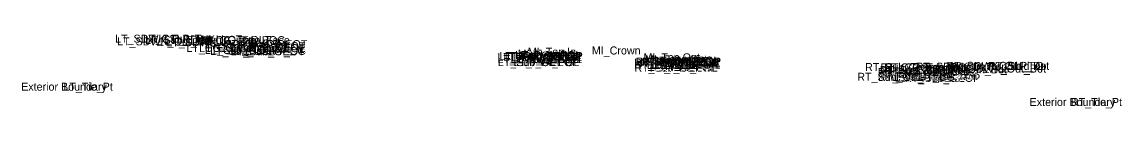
# Model space of a CAD drawing. Extents: x -26 to 6300, y -10 to 9528.
# Drawn here: x 1074.9 to 1212.4, y 7509.6 to 7518.8 of the extents above; entities that cross this region are included whole.
import ezdxf

# ---------------------------------------------------------------- set-up
doc = ezdxf.new("R2010")
doc.units = 0
doc.layers.add('Default', color=7, linetype='Continuous')

msp = doc.modelspace()

# ---------------------------------------------------------------- texts
at = {"layer": 'Default'}
for s, p in [('LT_SDWK_Out_Top', (1086.58, 7517.78)), ('LT_CSLP_Pnt', (1090.1, 7517.78)), ('LT_Sub_Trench_Out_DLT', (1090.32, 7517.63)), ('LT_SDWK_In_Top', (1092.74, 7517.68)), ('LT_CG_Top_BOC', (1096.81, 7517.59)), ('LT_CG_Top_Face', (1097.34, 7517.59)), ('LT_SDWK_Out_Bot', (1086.83, 7517.44)), ('LT_SDWK_In_Bot', (1092.99, 7517.34)), ('LT_CG1_Shelf_Out', (1095.48, 7516.62)), ('LT_CG_Bot_BOC', (1097.09, 7516.6)), ('LT_Sub_OEOP', (1097.79, 7516.38)), ('LT_CG_Top_Gut', (1097.87, 7517.09)), ('LT_Sub_OEOT_CG', (1098.44, 7516.25)), ('LT_PV2_OEOT', (1100.99, 7516.84)), ('LT_PV3_OEOT', (1100.99, 7516.59)), ('LT_Sub_OEOT', (1101.04, 7516.21)), ('LT_PV1_OEOT', (1101.23, 7517.09)), ('LT_CG_Bot_IE', (1101.34, 7516.5)), ('MI_Crown', (1146.15, 7516.3)), ('LT_PV2_OEEOP', (1134.36, 7515.47)), ('LT_PV3_OEEOP', (1134.36, 7515.22)), ('LT_Sub_OEEOP', (1134.41, 7514.85)), ('LT_PV1_OEEOP', (1134.6, 7515.6)), ('LT_PV2_IEEOP', (1135.12, 7515.47)), ('LT_PV1_IEEOP', (1135.36, 7515.6)), ('LT_PV2_PGL1', (1135.96, 7515.47)), ('LT_PV3_PGL1', (1135.96, 7515.22)), ('LT_PV2_PGL', (1136.34, 7515.47)), ('LT_PV4_PGL', (1136.34, 7514.85)), ('LT_PV1_PGL', (1136.58, 7515.72)), ('MI_Face In', (1136.88, 7515.89)), ('MI_Bot In', (1138.05, 7515.72)), ('MI_Top In', (1138.16, 7516.14)), ('RT_PV2_OEEOP', (1151.42, 7514.79)), ('RT_PV1_OEEOP', (1151.66, 7514.91)), ('RT_PV2_IEEOP', (1152.18, 7514.79)), ('RT_PV1_IEEOP', (1152.42, 7514.91)), ('MI_Top Out', (1152.6, 7515.45)), ('MI_Face Out', (1152.81, 7515.2)), ('RT_PV2_PGL1', (1153.02, 7514.79)), ('RT_PV2_PGL', (1153.4, 7514.79)), ('RT_PV1_PGL', (1153.63, 7515.04)), ('MI_Bot Out', (1154, 7515.04)), ('RT_PV3_OEEOP', (1151.42, 7514.54)), ('RT_Sub_OEEOP', (1151.46, 7514.16)), ('RT_PV3_PGL1', (1153.02, 7514.54)), ('RT_PV4_PGL', (1153.4, 7514.16)), ('RT_Sub_Trench_Out_DLT', (1180.29, 7514.23)), ('RT_PV2_OEOT', (1181.87, 7513.6)), ('RT_PV1_OEOT', (1182.11, 7513.85)), ('RT_CG_Top_Face', (1182.22, 7514.19)), ('RT_CG_Top_BOC', (1182.69, 7514.19)), ('RT_CG_Top_Gut', (1182.75, 7513.69)), ('RT_SDWK_In_Top', (1186.62, 7514.28)), ('RT_SDWK_In_Bot', (1186.87, 7513.94)), ('RT_SDWK_Out_Top', (1190.46, 7514.38)), ('RT_SDWK_Out_Bot', (1190.71, 7514.04)), ('RT_Shld_O', (1195.63, 7514.37)), ('CSLP_Pnt', (1197.04, 7514.38)), ('RT_Sub_OEOT_CG', (1179.32, 7513.01)), ('RT_PV3_OEOT', (1181.87, 7513.35)), ('RT_Sub_OEOT', (1181.92, 7512.97)), ('RT_CG_Bot_IE', (1182.22, 7513.26)), ('RT_CG1_Shelf_Out', (1182.36, 7513.14)), ('RT_CG_Bot_BOC', (1182.97, 7513.16)), ('RT_Sub_OEOP', (1185.17, 7512.88)), ('Exterior Boundary', (1074.84, 7511.78)), ('LT_Tie_Pt', (1080.12, 7511.78)), ('Exterior Boundary', (1200.85, 7509.86)), ('RT_Tie_Pt', (1206.01, 7509.86))]:
    msp.add_text(s, height=1, dxfattribs=at).set_placement(p)

doc.saveas('drawing.dxf')
